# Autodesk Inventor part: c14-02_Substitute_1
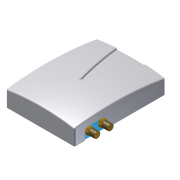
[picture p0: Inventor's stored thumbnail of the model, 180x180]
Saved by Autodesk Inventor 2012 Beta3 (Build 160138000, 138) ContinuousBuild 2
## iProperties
Created: 2011-01
Part Number: c14-02_Substitute_1
Material: Default
Document SubType Name: Modeling
Designer: Beta-8540w
Density: 1 g/cm^3
Author: Beta-8540w
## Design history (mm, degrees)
derived "c14-01.iam"
  node "c14-05.ipt:1"
body "Solid1"
node "c14-03.ipt:1"
node "Parker Hex Nipple 216P 216P-4:1"
node "Parker Hex Nipple 216P 216P-4:2"
sketch "c14-04.ipt:1"
workpoint "Work Point3"
workpoint "Work Point4"
workpoint "Work Point3_1"
workpoint "Work Point4_1"
workplane "Work Plane1"
